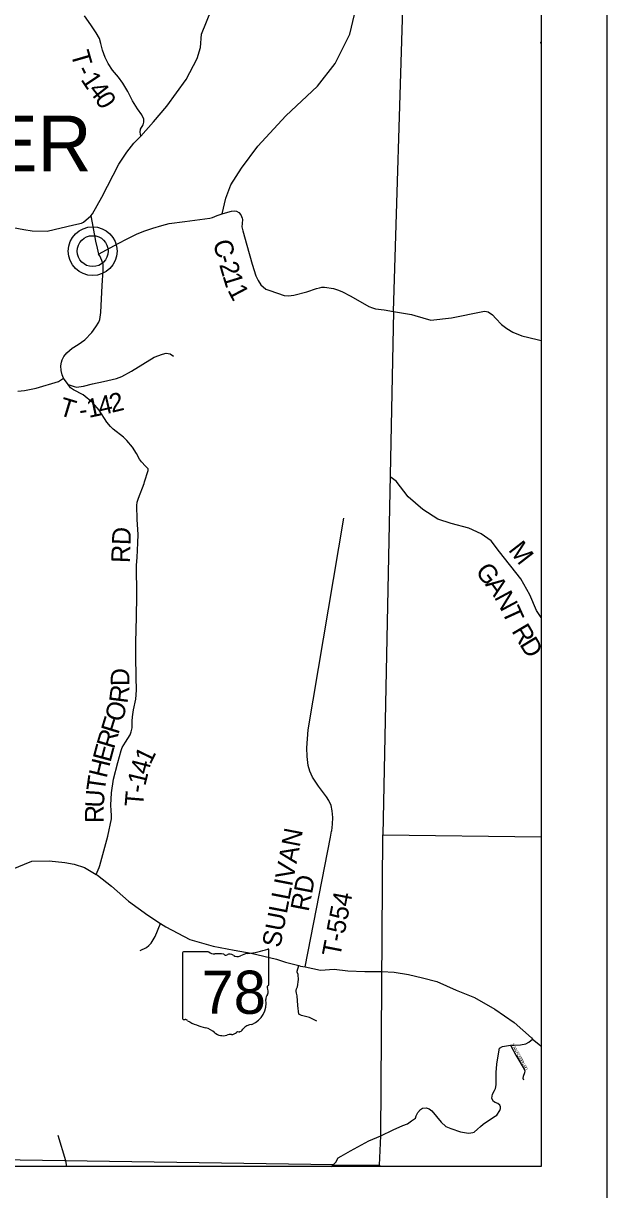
# Model space of a CAD drawing. Extents: x -22 to 431, y -18 to 160.
# Drawn here: x 330.215 to 331.995, y 147.609 to 151.169 of the extents above; entities that cross this region are included whole.
import ezdxf

# ---------------------------------------------------------------- set-up
doc = ezdxf.new("R2010")
doc.units = 0
for name, color, linetype in [('GM_X_Adjacent_County_Text', 7, 'Continuous'), ('GM_X_Airport_Location_Class_2', 7, 'Continuous'), ('GM_X_City_Street', 7, 'Continuous'), ('GM_X_City_Street_Text', 7, 'Continuous'), ('GM_X_County_Road', 7, 'Continuous'), ('GM_X_County_Road_Text', 7, 'Continuous'), ('GM_X_County_ROW', 7, 'Continuous'), ('GM_X_County_Subdivision', 7, 'Continuous'), ('GM_X_Major_River_Text', 7, 'Continuous'), ('GM_X_Minor_River_Text', 7, 'Continuous'), ('GM_X_Section', 7, 'Continuous'), ('GM_X_Township_Road', 7, 'Continuous'), ('GM_X_Township_ROW', 7, 'Continuous')]:
    doc.layers.add(name, color=color, linetype=linetype)

msp = doc.modelspace()

# ---------------------------------------------------------------- linework, layer by layer
at = {"layer": 'GM_X_Adjacent_County_Text'}
for points in [[(330.4213, 150.5812), (330.4257, 150.56), (330.4356, 150.5039), (330.4402, 150.483), (330.4451, 150.4651)], [(330.4451, 150.4651), (330.4451, 150.4651), (330.4694, 150.478), (330.5046, 150.497), (330.5323, 150.5111), (330.5608, 150.5252), (330.5831, 150.5347), (330.61, 150.5445), (330.6377, 150.5525), (330.6601, 150.5579), (330.7079, 150.5647), (330.7841, 150.575), (330.7928, 150.5765), (330.8065, 150.5822), (330.8216, 150.5879), (330.8319, 150.5913), (330.8501, 150.5955), (330.8592, 150.5967), (330.866, 150.5959), (330.8732, 150.5921), (330.8785, 150.5845), (330.8831, 150.5746), (330.8838, 150.5705), (330.8831, 150.5579), (330.8823, 150.5481), (330.8846, 150.5359), (330.8971, 150.4919), (330.9138, 150.4338), (330.9249, 150.3989), (330.9317, 150.3844), (330.94, 150.3715), (330.9556, 150.3582), (330.9674, 150.3537), (331.0114, 150.3381), (331.0246, 150.337), (331.0402, 150.3397), (331.0804, 150.3499), (331.1096, 150.3598), (331.1187, 150.3621), (331.1262, 150.3636), (331.1342, 150.364), (331.1615, 150.3594), (331.174, 150.356), (331.1869, 150.3507), (331.2142, 150.3363), (331.2689, 150.3052), (331.2806, 150.3006), (331.2897, 150.2976), (331.3162, 150.2947), (331.3449, 150.2891), (331.3996, 150.2804), (331.4098, 150.2774)], [(331.4098, 150.2774), (331.4581, 150.2635), (331.5218, 150.2699), (331.6174, 150.2901), (331.6234, 150.2909), (331.6333, 150.2886), (331.6462, 150.2799), (331.6572, 150.2681), (331.6743, 150.2502), (331.6906, 150.2381), (331.7084, 150.226), (331.7361, 150.215), (331.7831, 150.204), (331.7949, 150.2008)]]:
    msp.add_lwpolyline(points, dxfattribs=at)
at = {"layer": 'GM_X_Airport_Location_Class_2'}
for p, q in [((330.9647, 148.2352), (330.9647, 148.3399)), ((330.701, 148.3315), (330.701, 148.1314)), ((330.7808, 148.335), (330.7036, 148.335)), ((330.9647, 148.2353), (330.9647, 148.2352))]:
    msp.add_line(p, q, dxfattribs=at)
for centre, radius, start, end in [((330.8708, 148.6078), 0.2796, 275.8445, 288.9065), ((330.9618, 148.3404), 0.00294, 351.8621, 97.738), ((330.704, 148.3319), 0.00305, 98.1301, 188.1301), ((330.7992, 148.3582), 0.0296, 231.6195, 271.1119), ((330.809, 148.2226), 0.1064, 80.4867, 94.9883), ((330.8332, 148.333), 0.00855, 219.7921, 297.1024), ((330.8457, 148.3099), 0.0178, 54.4667, 119.1411), ((330.8687, 148.3416), 0.0214, 233.8562, 294.8282), ((330.9064, 148.2738), 0.0563, 97.3462, 120.7689), ((330.964, 148.2276), 0.00454, 107.944, 210.337), ((330.9616, 148.2348), 0.00314, 289.6038, 7.7341), ((330.9752, 148.1914), 0.0198, 136.8065, 186.9296), ((330.9351, 148.2143), 0.0273, 340.033, 23.6496), ((330.8864, 148.1781), 0.0699, 292.3089, 8.9858), ((330.7041, 148.131), 0.00308, 171.9584, 258.3066), ((330.7045, 148.1514), 0.0235, 267.339, 280.6039), ((330.7093, 148.1199), 0.00848, 29.7484, 93.2717), ((330.8164, 148.2997), 0.2019, 240.4129, 257.1985), ((330.7562, 148.0415), 0.0632, 47.1842, 75.836), ((330.8506, 148.1039), 0.0214, 268.777, 315.5493), ((330.8699, 148.0845), 0.00601, 65.7517, 132.6484), ((330.8674, 148.112), 0.0226, 282.8732, 323.2771), ((330.9159, 148.0752), 0.0383, 94.4031, 142.5768), ((330.8245, 148.1189), 0.0401, 230.7004, 286.2918), ((330.8477, 148.0497), 0.0329, 85.6951, 111.2099)]:
    msp.add_arc(centre, radius, start, end, dxfattribs=at)
at = {"layer": 'GM_X_County_Road'}
for points in [[(330.8216, 150.5879), (330.8328, 150.6354), (330.8488, 150.6765), (330.8807, 150.7269), (330.9307, 150.7941), (331.0165, 150.8866), (331.113, 150.9773), (331.1663, 151.0472), (331.2116, 151.1364), (331.2403, 151.2577), (331.2571, 151.3441), (331.3077, 151.4521), (331.3427, 151.4799), (331.3823, 151.5089), (331.3878, 151.5189)], [(331.1558, 148.7031), (331.1561, 148.7046), (331.1589, 148.7249), (331.1596, 148.7447), (331.158, 148.7657), (331.1541, 148.7817), (331.1476, 148.7964), (331.1402, 148.8082), (331.1163, 148.8401), (331.0976, 148.8678), (331.0896, 148.8862), (331.0844, 148.9038), (331.081, 148.9312), (331.0804, 148.9574), (331.0844, 149.0128), (331.1935, 149.6587)]]:
    msp.add_lwpolyline(points, dxfattribs=at)
at = {"layer": 'GM_X_County_ROW'}
for points in [[(330.1344, 150.555), (330.2174, 150.5399), (330.2425, 150.5361), (330.2881, 150.535), (330.3691, 150.5537), (330.3927, 150.5593), (330.3992, 150.5627), (330.4213, 150.5812), (330.4265, 150.5874), (330.4545, 150.6383), (330.5072, 150.7397), (330.531, 150.7758), (330.5523, 150.8035), (330.5735, 150.8248), (330.6127, 150.8687), (330.6534, 150.916), (330.7117, 150.9979), (330.7457, 151.0619), (330.7554, 151.0955), (330.7594, 151.1366), (330.8051, 151.2498)], [(330.179, 148.5862), (330.2413, 148.6111), (330.2944, 148.6127), (330.3423, 148.6077), (330.3709, 148.6021), (330.4018, 148.5923), (330.4381, 148.5708), (330.4413, 148.569), (330.4847, 148.5355), (330.5366, 148.4896), (330.5954, 148.4464), (330.6339, 148.4215), (330.6498, 148.4112), (330.7229, 148.3728), (330.7946, 148.3523), (330.8583, 148.3396), (330.9108, 148.3302), (330.9874, 148.312), (331.0156, 148.3033), (331.056, 148.2929), (331.0614, 148.2915), (331.0754, 148.2885), (331.1216, 148.2788), (331.1637, 148.282), (331.2049, 148.2763), (331.2572, 148.2748), (331.3092, 148.2748), (331.3468, 148.2725), (331.3899, 148.266), (331.433, 148.2557), (331.4765, 148.2446), (331.536, 148.218), (331.5918, 148.1957), (331.6538, 148.1598), (331.7129, 148.1193), (331.766, 148.0723), (331.769, 148.0682), (331.7879, 148.0524), (331.7949, 148.0463)]]:
    msp.add_lwpolyline(points, dxfattribs=at)
at = {"layer": 'GM_X_Major_River_Text'}
for p, q in [((331.3449, 150.2891), (331.3823, 151.5089)), ((331.3449, 150.2891), (331.3119, 148.6917)), ((331.306, 147.7727), (331.3119, 148.6917)), ((331.3119, 148.6917), (331.7949, 148.6858)), ((331.3024, 147.683), (331.306, 147.7727)), ((331.1607, 147.6846), (329.6058, 147.708)), ((331.1607, 147.6846), (331.3024, 147.683)), ((331.3024, 147.683), (331.3023, 147.6799)), ((331.3023, 147.6799), (331.3024, 147.683))]:
    msp.add_line(p, q, dxfattribs=at)
at = {"layer": 'GM_X_Minor_River_Text'}
for points in [[(330.5735, 150.8248), (330.5723, 150.8371), (330.5733, 150.8463), (330.5808, 150.8596), (330.583, 150.8672), (330.5826, 150.8767), (330.5772, 150.8899), (330.5638, 150.9088), (330.548, 150.933), (330.5338, 150.961), (330.5188, 150.9871), (330.5054, 151.0045), (330.4878, 151.0264), (330.4744, 151.0472), (330.4655, 151.065), (330.4574, 151.0873), (330.4519, 151.1082), (330.4473, 151.1226), (330.4373, 151.14), (330.4215, 151.1649), (330.402, 151.1925)], [(331.7949, 151.1064), (331.7944, 151.1116), (331.7949, 151.1132)], [(330.338, 150.0856), (330.3338, 150.0962), (330.331, 150.1094), (330.3301, 150.1242), (330.332, 150.1353), (330.3338, 150.1421), (330.339, 150.152), (330.3477, 150.1631), (330.3643, 150.1772), (330.3832, 150.1891), (330.4032, 150.203), (330.4246, 150.2251), (330.437, 150.2427), (330.446, 150.2572), (330.449, 150.2652), (330.4522, 150.2868), (330.4562, 150.3685), (330.4589, 150.4156), (330.4592, 150.4262), (330.4587, 150.4342), (330.4553, 150.4452), (330.4483, 150.4599), (330.4451, 150.4651)], [(330.3526, 150.0663), (330.3701, 150.0611), (330.3773, 150.0589), (330.3989, 150.0613), (330.4269, 150.0687), (330.4599, 150.0758), (330.5, 150.0848), (330.5163, 150.091), (330.545, 150.1071), (330.6148, 150.1498), (330.6402, 150.1598), (330.6516, 150.1622), (330.6629, 150.1607), (330.6732, 150.1536)], [(330.1983, 150.0466), (330.2188, 150.0483), (330.2544, 150.0554), (330.3229, 150.076), (330.338, 150.0856)], [(330.5836, 149.7648), (330.5837, 149.7649), (330.5854, 149.7696), (330.5965, 149.8046), (330.5965, 149.8091), (330.5881, 149.8178), (330.5758, 149.8306), (330.5701, 149.8389), (330.5608, 149.8563), (330.5486, 149.8752), (330.5313, 149.8956), (330.5206, 149.9058), (330.4894, 149.9306), (330.4813, 149.9381), (330.4702, 149.9513), (330.4464, 149.9888), (330.4277, 150.011), (330.3976, 150.0347), (330.3686, 150.0508), (330.3595, 150.0565), (330.3526, 150.0663), (330.338, 150.0856)], [(330.4486, 148.5986), (330.4486, 148.5986), (330.4734, 148.6878), (330.484, 148.741), (330.4847, 148.7505), (330.4834, 148.766), (330.4825, 148.7827), (330.4845, 148.8199), (330.4903, 148.8621), (330.504, 148.9127), (330.5136, 148.9492), (330.5165, 148.9583), (330.527, 148.9751), (330.5413, 148.9976), (330.5446, 149.006), (330.5472, 149.0189), (330.5478, 149.0386), (330.5481, 149.0523), (330.5517, 149.0732), (330.5583, 149.1063), (330.5601, 149.1196), (330.5608, 149.1344), (330.5598, 149.1719), (330.5589, 149.238), (330.559, 149.2805), (330.5611, 149.356), (330.5617, 149.4221), (330.5607, 149.5147), (330.5624, 149.539), (330.5647, 149.583), (330.5653, 149.6092), (330.5627, 149.6548), (330.562, 149.6973), (330.5627, 149.7071), (330.5668, 149.7197), (330.5836, 149.7648)], [(331.7949, 149.3558), (331.7809, 149.3764), (331.7601, 149.4244), (331.7332, 149.4739), (331.6681, 149.5562), (331.6428, 149.5895), (331.6123, 149.6105), (331.5746, 149.6281), (331.5207, 149.6425), (331.48, 149.6555), (331.4339, 149.6852), (331.3896, 149.7243), (331.3532, 149.7719), (331.3345, 149.7844)], [(331.0754, 148.2885), (331.1523, 148.6848), (331.1558, 148.7031)], [(330.4381, 148.5708), (330.4467, 148.592), (330.4486, 148.5986)], [(330.5716, 148.3388), (330.591, 148.348), (330.5985, 148.354), (330.6057, 148.3609), (330.6171, 148.3817), (330.6339, 148.4215)], [(331.1104, 148.1235), (331.0885, 148.1343), (331.0683, 148.1391), (331.0638, 148.1402), (331.0576, 148.143), (331.0557, 148.1445), (331.0531, 148.171), (331.0509, 148.2002), (331.0483, 148.209), (331.0475, 148.2137), (331.0478, 148.2171), (331.0487, 148.2215), (331.0514, 148.2283), (331.0546, 148.2508), (331.0547, 148.2548), (331.0541, 148.2601), (331.0535, 148.2659), (331.0507, 148.2727), (331.051, 148.2757), (331.056, 148.2929)], [(331.2135, 147.7271), (331.2694, 147.7575), (331.306, 147.7727), (331.3439, 147.7912), (331.3726, 147.805), (331.3871, 147.81), (331.3999, 147.8192), (331.4114, 147.8268), (331.4141, 147.8341), (331.419, 147.8443), (331.4266, 147.853), (331.4334, 147.858), (331.444, 147.8584), (331.4539, 147.8557), (331.4615, 147.8493), (331.4899, 147.8143), (331.5039, 147.8018), (331.5191, 147.795), (331.5491, 147.7848), (331.5734, 147.7814), (331.5806, 147.7817), (331.5862, 147.7829), (331.5908, 147.7844), (331.601, 147.7939), (331.6101, 147.8015), (331.6181, 147.8087), (331.6496, 147.8303), (331.6594, 147.8364), (331.6693, 147.8501), (331.6708, 147.8562), (331.6708, 147.8615), (331.6685, 147.8668), (331.6632, 147.8717), (331.6545, 147.8747), (331.6499, 147.8778), (331.6457, 147.8846), (331.6446, 147.8884), (331.6469, 147.9002), (331.6529, 147.9119), (331.6556, 147.918), (331.6582, 147.929), (331.6582, 147.9666), (331.6601, 147.9916), (331.6665, 148.036), (331.6684, 148.0402), (331.6771, 148.0459), (331.7017, 148.0498), (331.7321, 148.0505), (331.7488, 148.0539), (331.7575, 148.0585), (331.769, 148.0682)], [(330.3486, 147.6799), (330.3448, 147.6969), (330.3216, 147.7744)], [(331.1546, 147.6799), (331.1607, 147.6846), (331.1691, 147.693), (331.1755, 147.7054), (331.1847, 147.7114), (331.2135, 147.7271)]]:
    msp.add_lwpolyline(points, dxfattribs=at)
at = {"layer": 'GM_X_Section'}
for p, q in [((331.7949, 159.9199), (331.7949, 147.6799)), ((331.7949, 147.6799), (319.5549, 147.6799))]:
    msp.add_line(p, q, dxfattribs=at)
msp.add_lwpolyline([(319.3549, 160.1199), (331.9949, 160.1199), (331.9949, 147.4799), (319.3549, 147.4799)], close=True, dxfattribs=at)
at = {"layer": 'GM_X_Township_Road'}
for radius in [0.0744, 0.0472]:
    msp.add_circle((330.427, 150.4739), radius, dxfattribs=at)
at = {"layer": 'GM_X_Township_ROW'}
msp.add_lwpolyline([(331.7017, 148.0498), (331.7181, 148.0194), (331.7435, 147.9761), (331.7454, 147.9715), (331.7447, 147.9655), (331.7398, 147.9537), (331.739, 147.9495), (331.7409, 147.9442)], dxfattribs=at)

# ---------------------------------------------------------------- texts
at = {"layer": 'GM_X_Airport_Location_Class_2'}
msp.add_text('78', height=0.13184, dxfattribs=at).set_placement((330.7591, 148.1455))
at = {"layer": 'GM_X_City_Street'}
for s, rotation, p in [('C', 286.0955, (330.793, 150.5005)), ('2', 286.3196, (330.8125, 150.433)), ('-', 286.1489, (330.8059, 150.4556)), ('1', 287.0901, (330.8226, 150.3987)), ('1', 297.6081, (330.8372, 150.3547))]:
    msp.add_text(s, height=0.0568, rotation=rotation, dxfattribs=at).set_placement(p)
at = {"layer": 'GM_X_City_Street_Text'}
for s, height, rotation, p in [('T', 0.0568, 286.1332, (330.3594, 151.0771)), ('1', 0.0568, 303.6007, (330.389, 150.998)), ('-', 0.0568, 295.0722, (330.3746, 151.0272)), ('4', 0.0568, 308.0405, (330.4112, 150.965)), ('0', 0.0568, 301.5144, (330.4318, 150.9388)), ('T', 0.0568, 343.2404, (330.3208, 149.9744)), ('1', 0.0568, 11.9341, (330.4152, 149.9646)), ('4', 0.0568, 13.0237, (330.4506, 149.9721)), ('2', 0.0568, 13.5117, (330.4853, 149.9801)), ('-', 0.0568, 9.2682, (330.3894, 149.9603)), ('RD', 0.05682, 87.6365, (330.54, 149.521)), ('M', 0.0568, 307.7123, (331.6928, 149.5613)), ('G', 0.0568, 307.366, (331.5923, 149.4956)), ('A', 0.0568, 306.0255, (331.6225, 149.4561)), ('N', 0.0568, 298.284, (331.6508, 149.4174)), ('T', 0.0568, 294.5082, (331.6741, 149.3742)), ('R', 0.0568, 300.627, (331.7035, 149.3145)), ('D', 0.0568, 301.2567, (331.7276, 149.2738)), ('D', 0.0568, 90.9275, (330.5393, 149.1465)), ('R', 0.0568, 82.8172, (330.533, 149.0914)), ('O', 0.0568, 73.5434, (330.5168, 149.0337)), ('F', 0.0568, 72.8543, (330.5052, 148.9963)), ('R', 0.0568, 73.4118, (330.492, 148.9517)), ('E', 0.0568, 74.996, (330.4811, 148.9111)), ('1', 0.0568, 64.0424, (330.6032, 148.9041)), ('H', 0.0568, 76.3004, (330.4693, 148.8629)), ('4', 0.0568, 75.4551, (330.5954, 148.8731)), ('T', 0.0568, 81.9166, (330.4636, 148.8222)), ('1', 0.0568, 76.5115, (330.5874, 148.8393)), ('-', 0.0568, 81.5785, (330.5842, 148.8175)), ('U', 0.0568, 86.5445, (330.4607, 148.7735)), ('T', 0.0568, 85.2591, (330.5808, 148.7761)), ('R', 0.0568, 88.993, (330.4599, 148.7275)), ('SULLIVAN', 0.05682, 79.0679, (330.999, 148.3453)), ('RD', 0.05682, 79.0773, (331.0855, 148.4556)), ('T-554', 0.05682, 79.02, (331.1817, 148.3168))]:
    msp.add_text(s, height=height, rotation=rotation, dxfattribs=at).set_placement(p)
at = {"layer": 'GM_X_County_Road_Text'}
msp.add_text('CENTER', height=0.17045, rotation=0, dxfattribs=at).set_placement((329.4867, 150.7171))
at = {"layer": 'GM_X_County_Subdivision'}
for s, rotation, p in [('V', 298.2371, (331.7039, 148.0514)), ('A', 298.2382, (331.7078, 148.044)), ('N', 298.2382, (331.7117, 148.0367)), ('F', 298.2268, (331.7169, 148.0271)), ('O', 298.2382, (331.72, 148.0213)), ('S', 298.2383, (331.724, 148.0139)), ('S', 298.2268, (331.7271, 148.008)), ('E', 298.2268, (331.7303, 148.0022)), ('N', 298.2382, (331.7334, 147.9963)), ('R', 298.2382, (331.7386, 147.9868)), ('D', 298.2382, (331.7421, 147.9801))]:
    msp.add_text(s, height=0.00947, rotation=rotation, dxfattribs=at).set_placement(p)

doc.saveas('drawing.dxf')
